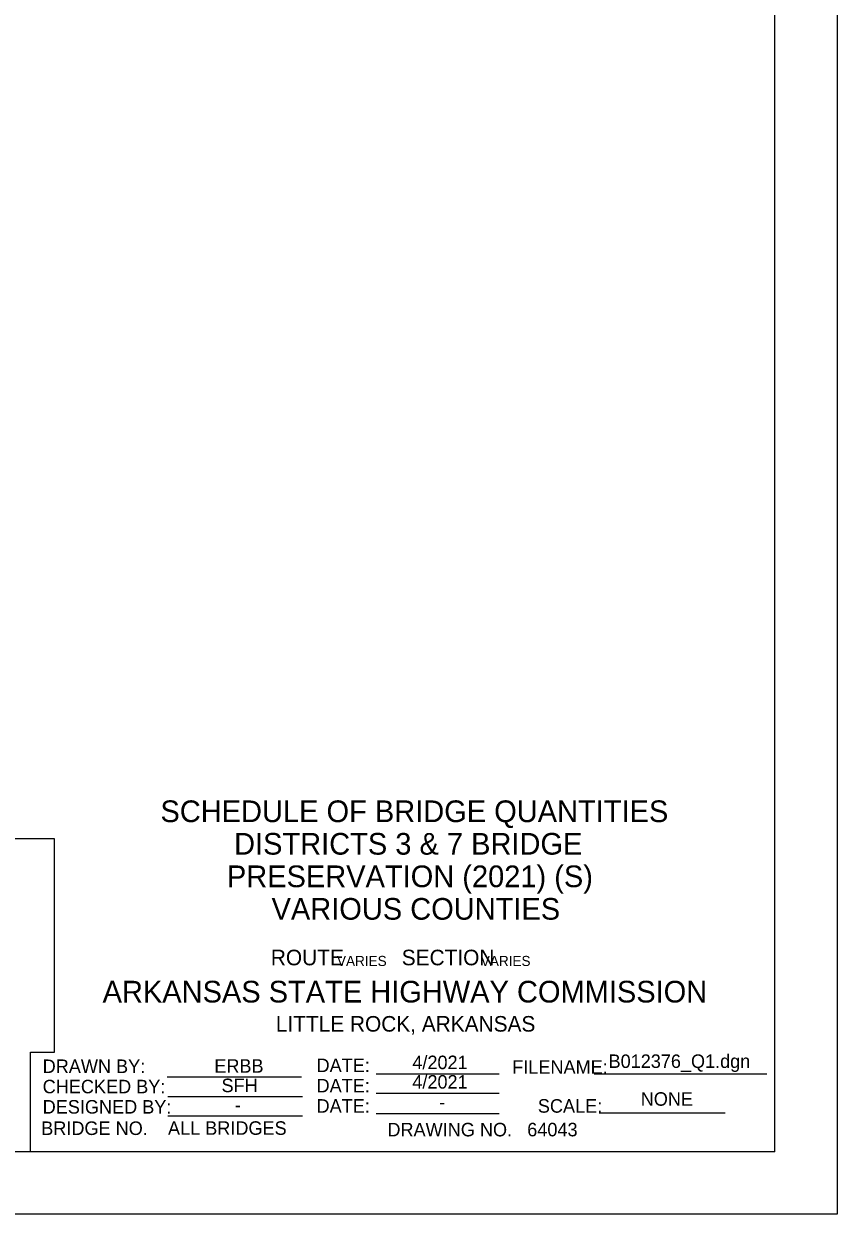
# Model space of a CAD drawing. Extents: x 16 to 1228740, y 11 to 152440.
# Drawn here: x 17.864 to 18.49, y 10.709 to 11.626 of the extents above; entities that cross this region are included whole.
import ezdxf

# ---------------------------------------------------------------- set-up
doc = ezdxf.new("R2010")
doc.units = 0
for name, color, linetype in [('B_Copy In', 7, 'Continuous'), ('B_Text', 7, 'Continuous'), ('B_Title Text', 7, 'Continuous'), ('R_Border', 7, 'Continuous'), ('R_No Plot', 7, 'Continuous')]:
    doc.layers.add(name, color=color, linetype=linetype)

msp = doc.modelspace()

# ---------------------------------------------------------------- linework, layer by layer
at = {"layer": 'B_Text'}
for p, q in [((18.13559, 10.81765), (18.23009, 10.81765)), ((18.30318, 10.81765), (18.43623, 10.81765)), ((17.97449, 10.81515), (18.07809, 10.81515)), ((17.97509, 10.80015), (18.07869, 10.80015)), ((18.13559, 10.80265), (18.23009, 10.80265)), ((18.13559, 10.80265), (18.23009, 10.80265)), ((17.97509, 10.78515), (18.07869, 10.78515)), ((18.13559, 10.78703), (18.23009, 10.78703)), ((18.30706, 10.78765), (18.40419, 10.78765))]:
    msp.add_line(p, q, dxfattribs=at)
at = {"layer": 'R_Border'}
for q in [(18.44221, 12.49475), (15.78327, 10.75755)]:
    msp.add_line((18.44221, 10.75755), q, dxfattribs=at)
msp.add_lwpolyline([(15.65694, 12.54282), (18.49027, 12.54282), (18.49027, 10.70949), (15.65694, 10.70949)], close=True, dxfattribs=at)
at = {"layer": 'R_No Plot'}
for p, q in [((17.888, 10.99864), (17.47349, 10.99864)), ((17.888, 10.83424), (17.888, 10.99864)), ((17.86946, 10.83424), (17.888, 10.83424)), ((17.86946, 10.75755), (17.86946, 10.83424))]:
    msp.add_line(p, q, dxfattribs=at)

# ---------------------------------------------------------------- texts
at = {"layer": 'B_Copy In'}
for s, height, p in [('SCHEDULE OF BRIDGE QUANTITIES', 0.0167, (17.96944, 11.01141)), ('DISTRICTS 3 & 7 BRIDGE', 0.0167, (18.02612, 10.98636)), ('PRESERVATION (2021) (S)', 0.0167, (18.02058, 10.96131)), ('VARIOUS COUNTIES', 0.0167, (18.05496, 10.93626)), ('ERBB', 0.0104, (18.01091, 10.81846)), ('4/2021', 0.0104, (18.16332, 10.82119)), ('B012376_Q1.dgn', 0.0104, (18.31434, 10.8221)), ('4/2021', 0.0104, (18.16332, 10.80619)), ('SFH', 0.0104, (18.01647, 10.80346)), ('NONE', 0.0104, (18.3391, 10.79302)), ('-', 0.0104, (18.02672, 10.78846)), ('-', 0.0104, (18.184, 10.79057)), ('ALL BRIDGES', 0.0104166, (17.97523, 10.7706)), ('64043', 0.010417, (18.25173, 10.76944))]:
    msp.add_text(s, height=height, dxfattribs=at).set_placement(p)
at = {"layer": 'B_Text'}
for s, height, p in [('DRAWN BY:', 0.010417, (17.87879, 10.8182)), ('DATE:', 0.010417, (18.08959, 10.8189)), ('FILENAME:', 0.010417, (18.24018, 10.81765)), ('CHECKED BY:', 0.0104166, (17.87879, 10.80257)), ('DATE:', 0.010417, (18.08959, 10.80328)), ('DESIGNED BY:', 0.0104166, (17.87879, 10.78695)), ('DATE:', 0.010417, (18.08959, 10.78765)), ('SCALE:', 0.010417, (18.25989, 10.78765)), ('BRIDGE NO.', 0.010417, (17.87767, 10.77048)), ('DRAWING NO.', 0.0104166, (18.14412, 10.76942))]:
    msp.add_text(s, height=height, dxfattribs=at).set_placement(p)
at = {"layer": 'B_Title Text'}
for s, height, p in [('ROUTE          SECTION ', 0.012, (18.0544, 10.90115)), ('                VARIES                         VARIES', 0.0078, (18.05893, 10.90059)), ('ARKANSAS STATE HIGHWAY COMMISSION', 0.0167, (17.92492, 10.8725)), ('LITTLE ROCK, ARKANSAS', 0.012, (18.05823, 10.85007))]:
    msp.add_text(s, height=height, dxfattribs=at).set_placement(p)

doc.saveas('drawing.dxf')
